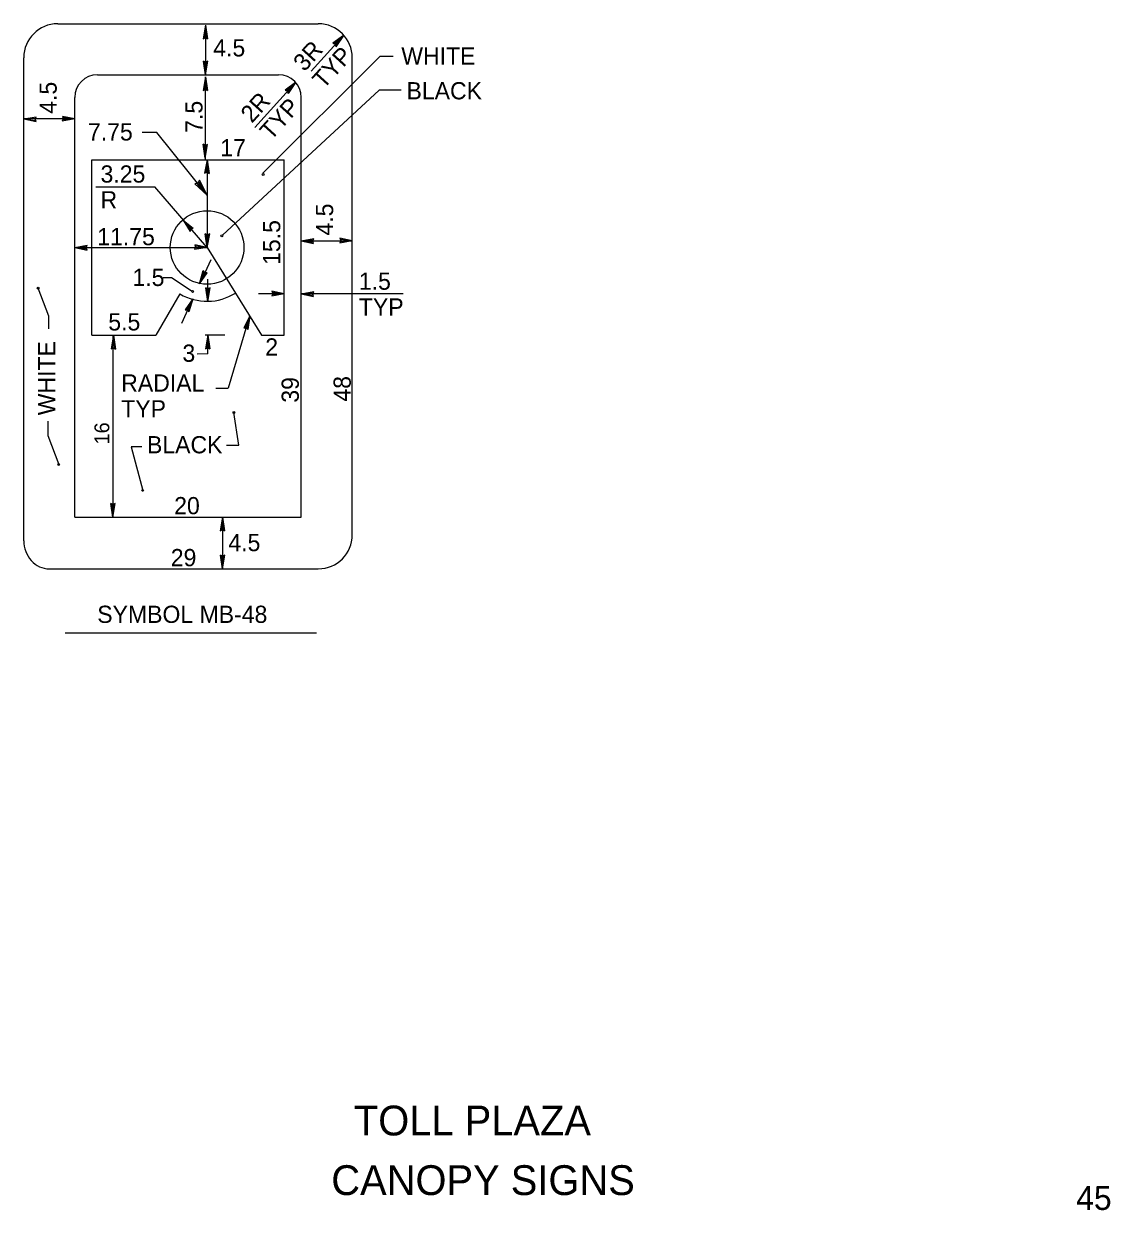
# Model space of a CAD drawing. Extents: x 60712 to 61344, y 9358 to 10016.
# Drawn here: x 61155.8 to 61338, y 9368.2 to 9567.2 of the extents above; entities that cross this region are included whole.
import ezdxf

# ---------------------------------------------------------------- set-up
doc = ezdxf.new("R2010")
doc.units = 0
for name, color, linetype in [('1', 7, 'Continuous'), ('21', 7, 'Continuous'), ('52', 7, 'Continuous'), ('Default', 7, 'Continuous'), ('GSBWFill', 7, 'Continuous'), ('TextMisc', 7, 'Continuous'), ('TextShtNo', 7, 'Continuous')]:
    doc.layers.add(name, color=color, linetype=linetype)

msp = doc.modelspace()

# ---------------------------------------------------------------- linework, layer by layer
at = {"layer": '1'}
for p, q in [((61215.51, 9561.67), (61195.89, 9542.12)), ((61217.71, 9561.67), (61215.51, 9561.67)), ((61215.37, 9556.05), (61189.09, 9531.7)), ((61219.09, 9556.05), (61215.37, 9556.05)), ((61178.11, 9548.94), (61175.63, 9548.94)), ((61186.55, 9538.45), (61178.11, 9548.94)), ((61186.52, 9529.65), (61191.29, 9521.99)), ((61159.97, 9518.13), (61158.18, 9522.84)), ((61159.97, 9516), (61159.97, 9518.13)), ((61191.84, 9496.52), (61191.01, 9501.99)), ((61159.83, 9500.53), (61159.83, 9498.1)), ((61159.83, 9498.1), (61161.63, 9493.24)), ((61175.59, 9496.22), (61173.8, 9496.22)), ((61173.8, 9496.22), (61175.73, 9488.92)), ((61189.77, 9496.52), (61191.84, 9496.52))]:
    msp.add_line(p, q, dxfattribs=at)
for centre in [(61195.92, 9541.9), (61188.99, 9531.59), (61158.18, 9522.84), (61191.01, 9501.99), (61161.63, 9493.24), (61175.72, 9488.92)]:
    msp.add_ellipse(centre, major_axis=(0, 0.157), ratio=0.906668, dxfattribs=at)
at = {"layer": '21'}
msp.add_line((61162.74, 9465.03), (61204.84, 9465.03), dxfattribs=at)
at = {"layer": '52'}
for p, q in [((61186.25, 9566.92), (61185.85, 9564.63)), ((61186.25, 9566.92), (61186.05, 9564.72)), ((61186.25, 9566.92), (61186.59, 9564.62)), ((61186.25, 9566.92), (61186.39, 9564.71)), ((61185.85, 9564.63), (61186.22, 9564.8)), ((61186.22, 9564.8), (61186.59, 9564.62)), ((61209.37, 9565.19), (61207.62, 9563.89)), ((61207.62, 9563.89), (61207.99, 9563.72)), ((61209.37, 9565.19), (61207.81, 9563.8)), ((61207.99, 9563.72), (61208.13, 9563.31)), ((61209.37, 9565.19), (61208.06, 9563.53)), ((61209.37, 9565.19), (61208.13, 9563.31)), ((61186.25, 9558.62), (61185.93, 9560.92)), ((61186.29, 9560.74), (61185.93, 9560.92)), ((61186.25, 9558.62), (61186.11, 9560.83)), ((61186.25, 9558.62), (61186.66, 9560.91)), ((61186.25, 9558.62), (61186.46, 9560.82)), ((61186.66, 9560.91), (61186.29, 9560.74)), ((61186.25, 9558.27), (61185.85, 9555.99)), ((61186.25, 9558.27), (61186.05, 9556.08)), ((61186.25, 9558.27), (61186.59, 9555.97)), ((61186.25, 9558.27), (61186.39, 9556.07)), ((61201.37, 9557.34), (61199.62, 9556.04)), ((61201.37, 9557.34), (61199.81, 9555.94)), ((61201.37, 9557.34), (61200.06, 9555.67)), ((61201.37, 9557.34), (61200.13, 9555.45)), ((61185.85, 9555.99), (61186.22, 9556.16)), ((61186.22, 9556.16), (61186.59, 9555.97)), ((61199.62, 9556.04), (61199.99, 9555.86)), ((61199.99, 9555.86), (61200.13, 9555.45)), ((61155.77, 9551.2), (61157.85, 9551.56)), ((61155.77, 9551.2), (61157.76, 9551.35)), ((61157.69, 9551.16), (61157.85, 9551.56)), ((61164.32, 9551.2), (61162.25, 9551.64)), ((61162.25, 9551.64), (61162.4, 9551.23)), ((61164.32, 9551.2), (61162.33, 9551.43)), ((61155.77, 9551.2), (61157.84, 9550.76)), ((61155.77, 9551.2), (61157.76, 9550.97)), ((61157.84, 9550.76), (61157.69, 9551.16)), ((61162.4, 9551.23), (61162.24, 9550.83)), ((61164.32, 9551.2), (61162.24, 9550.83)), ((61164.32, 9551.2), (61162.33, 9551.04)), ((61186.19, 9544.65), (61185.86, 9546.95)), ((61186.22, 9546.77), (61185.86, 9546.95)), ((61186.19, 9544.65), (61186.05, 9546.86)), ((61186.19, 9544.65), (61186.59, 9546.94)), ((61186.19, 9544.65), (61186.4, 9546.85)), ((61186.59, 9546.94), (61186.22, 9546.77)), ((61186.52, 9544.37), (61186.11, 9542.09)), ((61186.52, 9544.37), (61186.31, 9542.18)), ((61186.52, 9544.37), (61186.85, 9542.08)), ((61186.52, 9544.37), (61186.66, 9542.18)), ((61186.11, 9542.09), (61186.49, 9542.26)), ((61186.49, 9542.26), (61186.85, 9542.08)), ((61184.98, 9540.47), (61184.46, 9540.34)), ((61186.55, 9538.45), (61184.46, 9540.34)), ((61186.55, 9538.45), (61184.73, 9540.41)), ((61185.23, 9540.94), (61184.98, 9540.47)), ((61186.55, 9538.45), (61185.1, 9540.7)), ((61186.55, 9538.45), (61185.23, 9540.94)), ((61182.52, 9534.25), (61184.21, 9532.87)), ((61182.52, 9534.25), (61183.67, 9532.31)), ((61182.52, 9534.25), (61183.76, 9532.53)), ((61182.52, 9534.25), (61184.01, 9532.79)), ((61183.67, 9532.31), (61183.83, 9532.72)), ((61183.83, 9532.72), (61184.21, 9532.87)), ((61186.54, 9529.65), (61186.21, 9531.95)), ((61186.57, 9531.76), (61186.21, 9531.95)), ((61186.54, 9529.65), (61186.4, 9531.85)), ((61186.54, 9529.65), (61186.95, 9531.93)), ((61186.54, 9529.65), (61186.75, 9531.84)), ((61186.95, 9531.93), (61186.57, 9531.76)), ((61164.32, 9529.65), (61166.4, 9530.01)), ((61164.32, 9529.65), (61166.31, 9529.8)), ((61164.32, 9529.65), (61166.39, 9529.2)), ((61164.32, 9529.65), (61166.31, 9529.42)), ((61166.23, 9529.61), (61166.4, 9530.01)), ((61166.39, 9529.2), (61166.23, 9529.61)), ((61184.59, 9529.7), (61184.43, 9529.3)), ((61186.51, 9529.66), (61184.43, 9529.3)), ((61186.51, 9529.66), (61184.44, 9530.11)), ((61184.44, 9530.11), (61184.59, 9529.7)), ((61186.51, 9529.66), (61184.51, 9529.51)), ((61186.51, 9529.66), (61184.52, 9529.89)), ((61202.32, 9530.77), (61204.4, 9531.13)), ((61202.32, 9530.77), (61204.31, 9530.92)), ((61202.32, 9530.77), (61204.39, 9530.33)), ((61202.32, 9530.77), (61204.31, 9530.54)), ((61204.23, 9530.73), (61204.4, 9531.13)), ((61204.39, 9530.33), (61204.23, 9530.73)), ((61208.95, 9530.8), (61208.79, 9530.4)), ((61210.87, 9530.77), (61208.79, 9530.4)), ((61210.87, 9530.77), (61208.8, 9531.21)), ((61208.8, 9531.21), (61208.95, 9530.8)), ((61210.87, 9530.77), (61208.87, 9530.62)), ((61210.87, 9530.77), (61208.88, 9531)), ((61185.25, 9523.56), (61185.88, 9525.78)), ((61185.25, 9523.56), (61186.01, 9525.6)), ((61186.13, 9525.44), (61185.88, 9525.78)), ((61186.53, 9525.41), (61186.13, 9525.44)), ((61185.25, 9523.56), (61186.32, 9525.43)), ((61185.25, 9523.56), (61186.53, 9525.41)), ((61186.62, 9520.57), (61186.29, 9522.87)), ((61186.65, 9522.69), (61186.29, 9522.87)), ((61186.62, 9520.57), (61186.48, 9522.78)), ((61186.62, 9520.57), (61187.03, 9522.86)), ((61186.62, 9520.57), (61186.83, 9522.77)), ((61187.03, 9522.86), (61186.65, 9522.69)), ((61197.55, 9521.91), (61197.39, 9521.51)), ((61199.47, 9521.87), (61197.39, 9521.51)), ((61199.47, 9521.87), (61197.4, 9522.31)), ((61197.4, 9522.31), (61197.55, 9521.91)), ((61199.47, 9521.87), (61197.47, 9521.72)), ((61199.47, 9521.87), (61197.48, 9522.1)), ((61202.32, 9521.87), (61204.4, 9522.24)), ((61202.32, 9521.87), (61204.31, 9522.02)), ((61202.32, 9521.87), (61204.39, 9521.43)), ((61202.32, 9521.87), (61204.31, 9521.64)), ((61204.23, 9521.83), (61204.4, 9522.24)), ((61204.39, 9521.43), (61204.23, 9521.83)), ((61184.11, 9521.04), (61182.82, 9519.2)), ((61184.11, 9521.04), (61183.03, 9519.18)), ((61184.11, 9521.04), (61183.34, 9519.01)), ((61184.11, 9521.04), (61183.47, 9518.83)), ((61182.82, 9519.2), (61183.22, 9519.17)), ((61183.22, 9519.17), (61183.47, 9518.83)), ((61193.66, 9518.17), (61192.66, 9516.16)), ((61193.66, 9518.17), (61192.87, 9516.17)), ((61193.66, 9518.17), (61193.2, 9516.04)), ((61193.66, 9518.17), (61193.36, 9515.88)), ((61192.66, 9516.16), (61193.06, 9516.18)), ((61193.06, 9516.18), (61193.36, 9515.88)), ((61170.83, 9514.92), (61170.43, 9512.64)), ((61170.83, 9514.92), (61170.63, 9512.73)), ((61170.83, 9514.92), (61171.16, 9512.62)), ((61170.83, 9514.92), (61170.97, 9512.72)), ((61186.64, 9514.95), (61186.24, 9512.66)), ((61186.64, 9514.95), (61186.43, 9512.75)), ((61186.64, 9514.95), (61186.97, 9512.65)), ((61186.64, 9514.95), (61186.79, 9512.74)), ((61170.43, 9512.64), (61170.8, 9512.81)), ((61170.8, 9512.81), (61171.16, 9512.62)), ((61186.24, 9512.66), (61186.61, 9512.83)), ((61186.61, 9512.83), (61186.97, 9512.65)), ((61170.73, 9484.41), (61170.4, 9486.7)), ((61170.76, 9486.52), (61170.4, 9486.7)), ((61170.73, 9484.41), (61170.59, 9486.6)), ((61170.73, 9484.41), (61171.13, 9486.69)), ((61170.73, 9484.41), (61170.94, 9486.6)), ((61171.13, 9486.69), (61170.76, 9486.52)), ((61189.11, 9484.41), (61188.7, 9482.12)), ((61189.11, 9484.41), (61188.9, 9482.21)), ((61189.11, 9484.41), (61189.43, 9482.11)), ((61189.11, 9484.41), (61189.25, 9482.21)), ((61188.7, 9482.12), (61189.07, 9482.29)), ((61189.07, 9482.29), (61189.43, 9482.11)), ((61189.11, 9475.76), (61188.77, 9478.06)), ((61189.14, 9477.88), (61188.77, 9478.06)), ((61189.11, 9475.76), (61188.97, 9477.96)), ((61189.11, 9475.76), (61189.51, 9478.04)), ((61189.11, 9475.76), (61189.31, 9477.96)), ((61189.51, 9478.04), (61189.14, 9477.88))]:
    msp.add_line(p, q, dxfattribs=at)
at = {"layer": 'Default'}
for p, q in [((61186.52, 9544.37), (61186.52, 9529.68)), ((61202.32, 9530.77), (61210.87, 9530.77)), ((61187.14, 9527.58), (61185.49, 9523.94)), ((61179.16, 9524.6), (61180.53, 9524.6)), ((61180.53, 9524.6), (61184.01, 9522.35)), ((61219.4, 9521.87), (61202.32, 9521.87)), ((61189.5, 9514.95), (61186.17, 9514.95)), ((61189.11, 9484.41), (61189.11, 9475.76))]:
    msp.add_line(p, q, dxfattribs=at)
msp.add_circle((61186.52, 9529.65), 6.17, dxfattribs=at)
msp.add_ellipse((61184.09, 9522.27), major_axis=(0, 0.157), ratio=0.906668, dxfattribs=at)
at = {"layer": 'GSBWFill'}
for p, q in [((61161.47, 9567.17), (61205.17, 9567.17)), ((61186.25, 9566.92), (61186.25, 9558.62)), ((61203.97, 9559.24), (61209.37, 9565.19)), ((61155.77, 9480.48), (61155.77, 9561.47)), ((61210.87, 9481.46), (61210.87, 9561.47)), ((61168.12, 9558.62), (61198.52, 9558.62)), ((61186.25, 9544.37), (61186.25, 9558.27)), ((61194.52, 9549.78), (61201.37, 9557.34)), ((61164.32, 9484.41), (61164.32, 9554.82)), ((61202.32, 9484.41), (61202.32, 9554.82)), ((61164.32, 9551.2), (61155.77, 9551.2)), ((61167.17, 9514.92), (61167.17, 9544.37)), ((61167.17, 9544.37), (61199.47, 9544.37)), ((61199.47, 9514.95), (61199.47, 9544.37)), ((61167.87, 9539.8), (61177.73, 9539.8)), ((61186.45, 9529.71), (61177.73, 9539.8)), ((61164.32, 9529.65), (61186.52, 9529.65)), ((61186.62, 9520.57), (61186.62, 9524.33)), ((61181.97, 9521.85), (61177.92, 9514.92)), ((61191.29, 9521.99), (61195.67, 9514.95)), ((61199.47, 9521.87), (61195.13, 9521.87)), ((61184.08, 9520.99), (61182.24, 9516.92)), ((61193.65, 9518.14), (61190.04, 9506.07)), ((61167.17, 9514.92), (61177.92, 9514.92)), ((61170.73, 9514.92), (61170.73, 9484.41)), ((61186.64, 9511.8), (61186.64, 9514.95)), ((61195.67, 9514.95), (61199.47, 9514.95)), ((61186.64, 9511.8), (61184.86, 9511.76)), ((61188, 9506.07), (61190.04, 9506.07)), ((61164.32, 9484.41), (61202.32, 9484.41)), ((61160.04, 9475.76), (61205.17, 9475.76))]:
    msp.add_line(p, q, dxfattribs=at)
for centre, radius, start, end in [((61161.47, 9561.47), 5.7, 90, 180), ((61205.17, 9561.47), 5.7, 0, 90), ((61168.12, 9554.82), 3.8, 90, 180), ((61198.52, 9554.82), 3.8, 0, 90), ((61186.52, 9529.65), 9.02, 239.7206, 301.9049), ((61205.17, 9481.46), 5.7, 270, 360)]:
    msp.add_arc(centre, radius, start, end, dxfattribs=at)
msp.add_ellipse((61160.04, 9480.47), major_axis=(0, 4.71), ratio=0.906668, start_param=1.570796, end_param=3.141593, dxfattribs=at)

# ---------------------------------------------------------------- texts
at = {"layer": '1'}
for s, height, p in [('WHITE', 2.886, (61219.09, 9560.33)), ('BLACK', 2.886, (61219.96, 9554.49)), ('17', 2.886, (61188.72, 9544.93)), ('RADIAL', 2.886, (61172.12, 9505.48)), ('TYP', 2.886, (61172.12, 9501.15)), ('BLACK', 2.886, (61176.44, 9495.13)), ('20', 2.886, (61181, 9484.91)), ('29', 2.886, (61180.43, 9476.2)), ('SYMBOL MB-48', 2.8859, (61168.1, 9466.69))]:
    msp.add_text(s, height=height, dxfattribs=at).set_placement(p)
for s, height, p in [('15.5', 2.886, (61198.79, 9526.73)), ('WHITE', 2.886, (61161.05, 9501.51)), ('39', 2.886, (61201.9, 9503.62)), ('48', 2.886, (61210.61, 9503.8)), ('16', 2.489, (61170.12, 9496.62))]:
    msp.add_text(s, height=height, rotation=90, dxfattribs=at).set_placement(p)
at = {"layer": 'Default'}
for s, height, p in [('4.5', 2.886, (61187.55, 9561.69)), ('7.75', 2.886, (61166.54, 9547.59)), ('3.25', 2.886, (61168.65, 9540.53)), ('R', 2.89, (61168.65, 9536.2)), ('11.75', 2.886, (61168.1, 9530.03)), ('1.5', 2.886, (61174, 9523.19)), ('1.5', 2.886, (61211.97, 9522.56)), ('TYP', 2.886, (61211.97, 9518.23)), ('5.5', 2.886, (61169.95, 9515.73)), ('2', 2.89, (61196.27, 9511.52)), ('3', 2.89, (61182.38, 9510.48)), ('4.5', 2.886, (61190.09, 9478.72))]:
    msp.add_text(s, height=height, dxfattribs=at).set_placement(p)
for s, rotation, p in [('3R', 47.8024, (61202.84, 9559.01)), ('TYP', 47.8024, (61206.05, 9556.1)), ('4.5', 90, (61161.3, 9552.07)), ('2R', 47.8024, (61194.03, 9550.38)), ('7.5', 90, (61185.75, 9548.88)), ('TYP', 47.8024, (61197.24, 9547.48)), ('4.5', 90, (61207.66, 9531.65))]:
    msp.add_text(s, height=2.886, rotation=rotation, dxfattribs=at).set_placement(p)
at = {"layer": 'TextMisc'}
for s, p in [('       TOLL PLAZA       ', (61198.13, 9380.74)), ('      CANOPY SIGNS      ', (61196.2, 9370.74))]:
    msp.add_text(s, height=5, rotation=360, dxfattribs=at).set_placement(p)
at = {"layer": 'TextShtNo'}
msp.add_text('45', height=4, rotation=360, dxfattribs=at).set_placement((61332.26, 9368.24))

doc.saveas('drawing.dxf')
